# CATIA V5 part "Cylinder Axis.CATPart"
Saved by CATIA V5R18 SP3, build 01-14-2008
Part number: Moving Part02
Bounding box of the stored display mesh (mm): x -32.499 to 32.499, y 0 to 170, z -32.499 to 32.499
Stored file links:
  E:\#00 CATIA V5 Movie\#03 CATIA V5 Data\#07 KIN\Balance Unit (1)\Cylinder Axis.CATPart
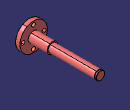
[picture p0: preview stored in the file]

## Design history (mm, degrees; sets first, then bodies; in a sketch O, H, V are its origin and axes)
Body1 (main body)
  Sketch1 on yz-plane, origin (0, 0, 0), H (0, 1, 0), V (0, 0, 1)
    line L1 (0, 0) -> (0, 32.5)
    line L2 (0, 32.5) -> (10, 32.5)
    line L3 (10, 32.5) -> (10, 12.5)
    line L4 (10, 12.5) -> (55, 12.5)
    point P4 (55, 12.5)
    line L5 (55, 12.5) -> (55, 10)
    line L6 (55, 10) -> (165, 10)
    line L7 (165, 10) -> (165, 9.5)
    point P7 (165, 9.5)
    line L8 (165, 9.5) -> (166.35, 9.5)
    line L9 (166.35, 9.5) -> (166.35, 10)
    point P9 (166.35, 10)
    line L10 (166.35, 10) -> (170, 10)
    line L11 (170, 10) -> (170, 0)
    point P11 (170, 0)
    length L2 = 10
    distance L2 H = 32.5
    distance L4 H = 12.5
    distance L6 H = 10
    distance P4 L3 = 45
    distance L11 L7 = 5
    distance L9 L7 = 1.35
    distance P7 H = 9.5
    distance L11 L1 = 170
    vertical: L1 V, L3 V, L5 V, L7 V, L9 V, L11 V
    horizontal: L2 H, L4 H, L6 H, L8 H, L10 H
    coincidence: P9 L6, P11 H
  Shaft1: profile Sketch1, axis Sketch1.H, angle 360
  Chamfer1: length 0.5, second length 0.5, on edge [face of Shaft1 from Sketch1.L10 | face of Shaft1 from Sketch1.L11]
  Sketch2 on face of Shaft1 from Sketch1.L1, origin (0, 0, 0), H (1, 0, 0), V (0, 0, 1)
    circle A1 centre (0, 0) radius 10
    radius A1 = 10
  Pocket1: profile Sketch2, direction (0, 1, 0), length 4
  Sketch3 on face of Shaft1 from Sketch1.L1, origin (0, 0, 25), H (1, 0, 0), V (0, 0, 1)
    point P1 (0, 0)
    reference projected point E1 (0, 0) from Sketch4.P1
    coincidence: E1 P1
  Hole1: placed by Sketch3, at (0, 0, 25) direction (0, 1, 0), diameter 9, through (limit type 6)
  CircPattern1: of Hole1, instances 4, angular step 90, axis from face of Shaft1 from Sketch1.L1
  Sketch4 on face of Shaft1 from Sketch1.L1, origin (0, 0, 0), H (1, 0, 0), V (0, 0, 1)
    point P1 (0, 25)
    distance P1 H = 25
    coincidence: P1 V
